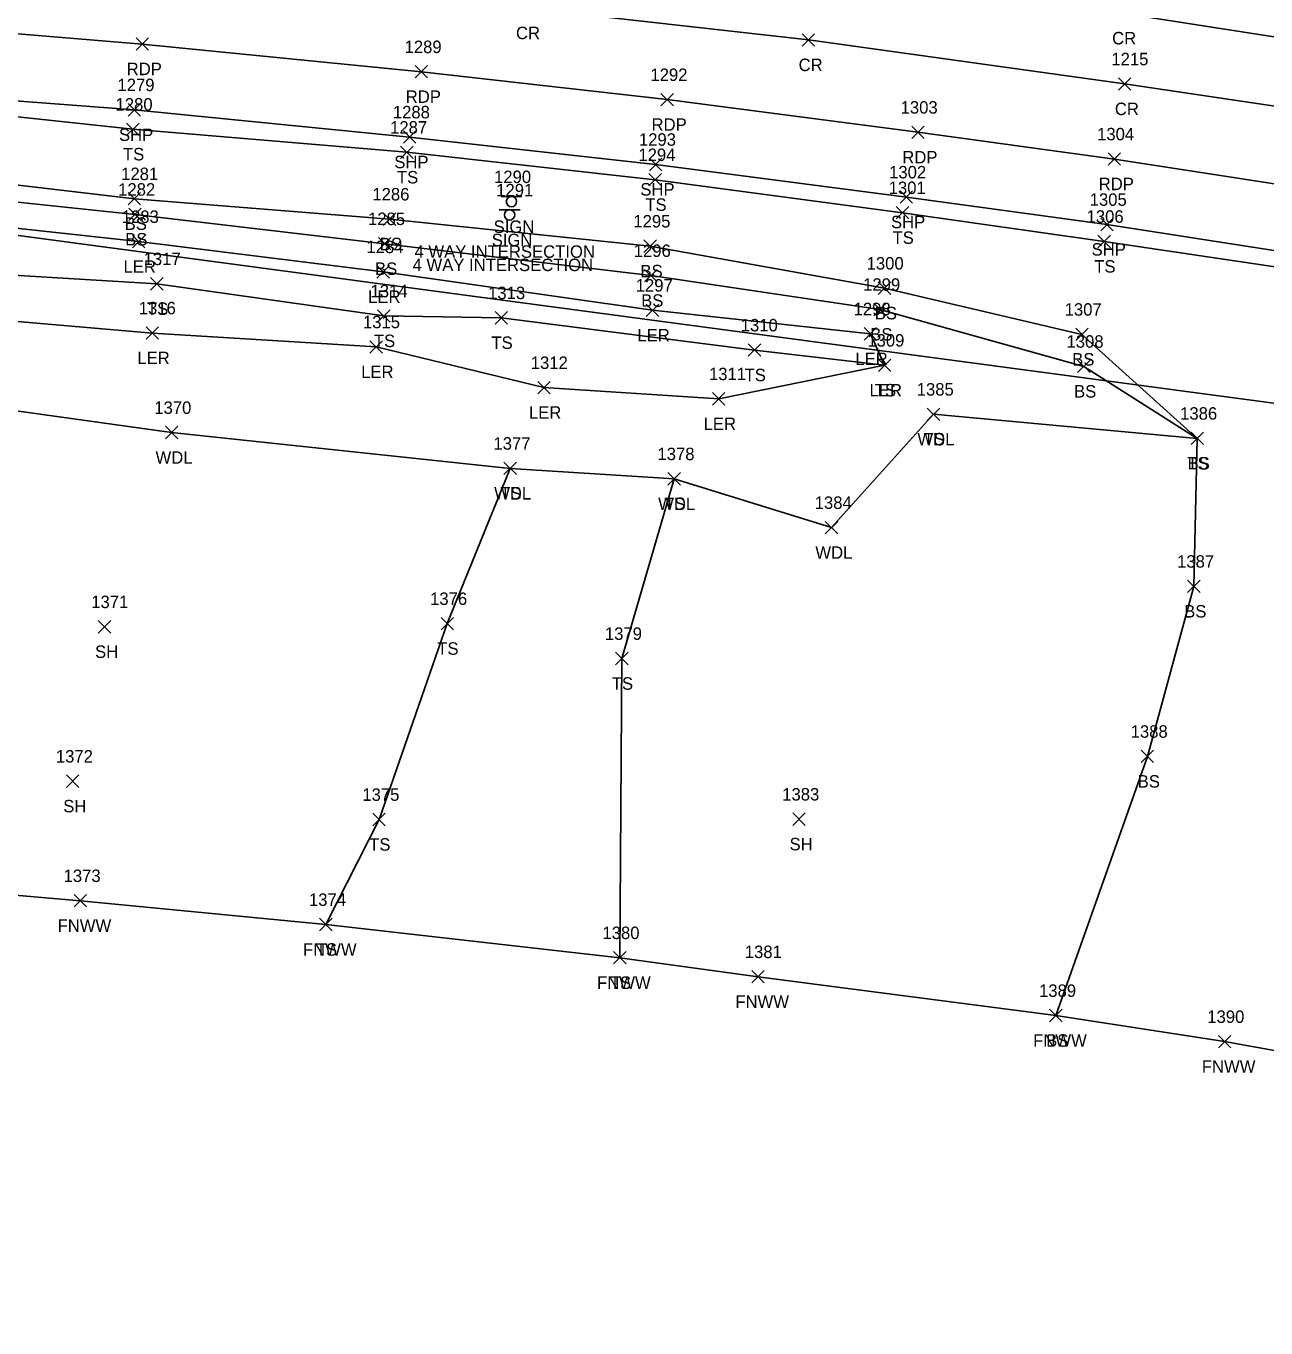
# Model space of a CAD drawing. Extents: x 1629176 to 1637209, y 606063 to 610167.
# Drawn here: x 1629364 to 1629563.1, y 606838.2 to 607047.2 of the extents above; entities that cross this region are included whole.
import ezdxf

# ---------------------------------------------------------------- set-up
doc = ezdxf.new("R2010")
doc.units = 0
for name, color, linetype in [('DCP', 7, 'Continuous'), ('L_A', 7, 'Continuous'), ('L_I', 7, 'Continuous'), ('L_TIC', 7, 'Continuous'), ('LARO', 7, 'Continuous'), ('LAWA', 7, 'Continuous'), ('LELB', 7, 'Continuous'), ('LFNC', 7, 'Continuous'), ('P_A', 7, 'Continuous'), ('P_I', 7, 'Continuous'), ('P_TIC', 7, 'Continuous'), ('PET', 7, 'Continuous'), ('PRC', 7, 'Continuous'), ('PSP', 7, 'Continuous'), ('S_A', 7, 'Continuous'), ('S_C', 7, 'Continuous'), ('S_I', 7, 'Continuous'), ('SSGN', 7, 'Continuous')]:
    doc.layers.add(name, color=color, linetype=linetype)

msp = doc.modelspace()

# ---------------------------------------------------------------- linework, layer by layer
at = {"layer": 'DCP'}
msp.add_lwpolyline([(1629240.18, 607029.98), (1629577.96, 606984.89)], dxfattribs=at)
at = {"layer": 'L_TIC'}
for points in [[(1629380.18, 607029.68), (1629382.18, 607031.68)], [(1629382.18, 607029.68), (1629380.18, 607031.68)], [(1629424.17, 607025.98), (1629426.17, 607027.98)], [(1629426.17, 607025.98), (1629424.17, 607027.98)], [(1629464.04, 607021.58), (1629466.04, 607023.58)], [(1629466.04, 607021.58), (1629464.04, 607023.58)], [(1629380.42, 607018.52), (1629382.42, 607020.52)], [(1629382.42, 607018.52), (1629380.42, 607020.52)], [(1629380.51, 607016.02), (1629382.51, 607018.02)], [(1629382.51, 607016.02), (1629380.51, 607018.02)], [(1629503.73, 607016.28), (1629505.73, 607018.28)], [(1629505.73, 607016.28), (1629503.73, 607018.28)], [(1629421.38, 607015.25), (1629423.38, 607017.25)], [(1629423.38, 607015.25), (1629421.38, 607017.25)], [(1629381.1, 607011.64), (1629383.1, 607013.64)], [(1629383.1, 607011.64), (1629381.1, 607013.64)], [(1629420.62, 607011.3), (1629422.62, 607013.3)], [(1629422.62, 607011.3), (1629420.62, 607013.3)], [(1629536.12, 607011.67), (1629538.12, 607013.67)], [(1629538.12, 607011.67), (1629536.12, 607013.67)], [(1629463.23, 607010.91), (1629465.23, 607012.91)], [(1629465.23, 607010.91), (1629463.23, 607012.91)], [(1629420.37, 607006.8), (1629422.37, 607008.8)], [(1629422.37, 607006.8), (1629420.37, 607008.8)], [(1629463.34, 607006.18), (1629465.34, 607008.18)], [(1629465.34, 607006.18), (1629463.34, 607008.18)], [(1629384.03, 607004.87), (1629386.03, 607006.87)], [(1629386.03, 607004.87), (1629384.03, 607006.87)], [(1629500.84, 607004.16), (1629502.84, 607006.16)], [(1629502.84, 607004.16), (1629500.84, 607006.16)], [(1629500.12, 607000.75), (1629502.12, 607002.75)], [(1629502.12, 607000.75), (1629500.12, 607002.75)], [(1629420.47, 606999.71), (1629422.47, 607001.71)], [(1629422.47, 606999.71), (1629420.47, 607001.71)], [(1629439.33, 606999.41), (1629441.33, 607001.41)], [(1629441.33, 606999.41), (1629439.33, 607001.41)], [(1629463.6, 607000.62), (1629465.6, 607002.62)], [(1629465.6, 607000.62), (1629463.6, 607002.62)], [(1629383.31, 606996.97), (1629385.31, 606998.97)], [(1629385.31, 606996.97), (1629383.31, 606998.97)], [(1629498.59, 606996.83), (1629500.59, 606998.83)], [(1629500.59, 606996.83), (1629498.59, 606998.83)], [(1629532.54, 606996.75), (1629534.54, 606998.75)], [(1629534.54, 606996.75), (1629532.54, 606998.75)], [(1629419.24, 606994.74), (1629421.24, 606996.74)], [(1629421.24, 606994.74), (1629419.24, 606996.74)], [(1629479.98, 606994.23), (1629481.98, 606996.23)], [(1629481.98, 606994.23), (1629479.98, 606996.23)], [(1629500.87, 606991.79), (1629502.87, 606993.79)], [(1629502.87, 606991.79), (1629500.87, 606993.79)], [(1629500.87, 606991.79), (1629502.87, 606993.79)], [(1629502.87, 606991.79), (1629500.87, 606993.79)], [(1629532.84, 606991.61), (1629534.84, 606993.61)], [(1629534.84, 606991.61), (1629532.84, 606993.61)], [(1629446.18, 606988.2), (1629448.18, 606990.2)], [(1629448.18, 606988.2), (1629446.18, 606990.2)], [(1629474.23, 606986.4), (1629476.23, 606988.4)], [(1629476.23, 606986.4), (1629474.23, 606988.4)], [(1629508.72, 606983.93), (1629510.72, 606985.93)], [(1629510.72, 606983.93), (1629508.72, 606985.93)], [(1629508.72, 606983.93), (1629510.72, 606985.93)], [(1629510.72, 606983.93), (1629508.72, 606985.93)], [(1629386.4, 606980.99), (1629388.4, 606982.99)], [(1629388.4, 606980.99), (1629386.4, 606982.99)], [(1629551.06, 606980.06), (1629553.06, 606982.06)], [(1629553.06, 606980.06), (1629551.06, 606982.06)], [(1629551.06, 606980.06), (1629553.06, 606982.06)], [(1629553.06, 606980.06), (1629551.06, 606982.06)], [(1629551.06, 606980.06), (1629553.06, 606982.06)], [(1629553.06, 606980.06), (1629551.06, 606982.06)], [(1629440.76, 606975.24), (1629442.76, 606977.24)], [(1629442.76, 606975.24), (1629440.76, 606977.24)], [(1629440.76, 606975.24), (1629442.76, 606977.24)], [(1629442.76, 606975.24), (1629440.76, 606977.24)], [(1629467.09, 606973.56), (1629469.09, 606975.56)], [(1629469.09, 606973.56), (1629467.09, 606975.56)], [(1629467.09, 606973.56), (1629469.09, 606975.56)], [(1629469.09, 606973.56), (1629467.09, 606975.56)], [(1629492.34, 606965.73), (1629494.34, 606967.73)], [(1629494.34, 606965.73), (1629492.34, 606967.73)], [(1629550.51, 606956.3), (1629552.51, 606958.3)], [(1629552.51, 606956.3), (1629550.51, 606958.3)], [(1629375.62, 606949.81), (1629377.62, 606951.81)], [(1629377.62, 606949.81), (1629375.62, 606951.81)], [(1629430.65, 606950.32), (1629432.65, 606952.32)], [(1629432.65, 606950.32), (1629430.65, 606952.32)], [(1629458.67, 606944.71), (1629460.67, 606946.71)], [(1629460.67, 606944.71), (1629458.67, 606946.71)], [(1629543.06, 606929), (1629545.06, 606931)], [(1629545.06, 606929), (1629543.06, 606931)], [(1629370.51, 606925.02), (1629372.51, 606927.02)], [(1629372.51, 606925.02), (1629370.51, 606927.02)], [(1629419.71, 606918.87), (1629421.71, 606920.87)], [(1629421.71, 606918.87), (1629419.71, 606920.87)], [(1629487.12, 606918.92), (1629489.12, 606920.92)], [(1629489.12, 606918.92), (1629487.12, 606920.92)], [(1629371.75, 606905.84), (1629373.75, 606907.84)], [(1629373.75, 606905.84), (1629371.75, 606907.84)], [(1629411.15, 606902.01), (1629413.15, 606904.01)], [(1629413.15, 606902.01), (1629411.15, 606904.01)], [(1629411.15, 606902.01), (1629413.15, 606904.01)], [(1629413.15, 606902.01), (1629411.15, 606904.01)], [(1629458.35, 606896.68), (1629460.35, 606898.68)], [(1629460.35, 606896.68), (1629458.35, 606898.68)], [(1629458.35, 606896.68), (1629460.35, 606898.68)], [(1629460.35, 606896.68), (1629458.35, 606898.68)], [(1629480.55, 606893.63), (1629482.55, 606895.63)], [(1629482.55, 606893.63), (1629480.55, 606895.63)], [(1629528.36, 606887.4), (1629530.36, 606889.4)], [(1629530.36, 606887.4), (1629528.36, 606889.4)], [(1629528.36, 606887.4), (1629530.36, 606889.4)], [(1629530.36, 606887.4), (1629528.36, 606889.4)], [(1629555.45, 606883.22), (1629557.45, 606885.22)], [(1629557.45, 606883.22), (1629555.45, 606885.22)]]:
    msp.add_lwpolyline(points, dxfattribs=at)
at = {"layer": 'LARO'}
msp.add_lwpolyline([(1629195.7, 607018.37), (1629216.28, 607024.93), (1629260.85, 607020.82), (1629301.15, 607020.1), (1629339.28, 607017.31), (1629382.1, 607012.64), (1629421.37, 607007.8), (1629464.6, 607001.62), (1629499.59, 606997.83), (1629501.87, 606992.79), (1629475.23, 606987.4), (1629447.18, 606989.2), (1629420.24, 606995.74), (1629384.31, 606997.97), (1629356.39, 607000.37), (1629322.81, 607000.42), (1629287.21, 607005.07), (1629251.47, 607005.2), (1629215.89, 607011.05), (1629196.49, 607014.19)], dxfattribs=at)
at = {"layer": 'LAWA'}
msp.add_lwpolyline([(1629337.05, 606990.15), (1629359.72, 606985.87), (1629387.4, 606981.99), (1629441.76, 606976.24), (1629468.09, 606974.56), (1629493.34, 606966.73), (1629509.72, 606984.93)], dxfattribs=at)
at = {"layer": 'LELB'}
for points in [[(1629181.05, 607042.55), (1629218.81, 607041.26), (1629263.39, 607039.5), (1629300.16, 607037.35), (1629342.16, 607034.85), (1629381.18, 607030.68), (1629425.17, 607026.98), (1629465.04, 607022.58), (1629504.73, 607017.28), (1629537.12, 607012.67), (1629575, 607007.04)], [(1629180.91, 607031.69), (1629217.04, 607032.99), (1629236.75, 607031.7), (1629261.62, 607030.75), (1629301.07, 607026.9), (1629340.53, 607024.3), (1629381.42, 607019.52), (1629422.38, 607016.25), (1629464.23, 607011.91), (1629501.84, 607005.16), (1629533.54, 606997.75), (1629552.06, 606981.06), (1629551.51, 606957.3), (1629544.06, 606930), (1629529.36, 606888.4)], [(1629180.79, 607027.59), (1629216.43, 607030.07), (1629237.58, 607029.18), (1629260.92, 607027.55), (1629301.36, 607024.43), (1629339.78, 607021.36), (1629381.51, 607017.02), (1629421.62, 607012.3), (1629464.34, 607007.18), (1629501.12, 607001.75), (1629533.84, 606992.61), (1629552.06, 606981.06)], [(1629501.87, 606992.79), (1629480.98, 606995.23), (1629440.33, 607000.41), (1629421.47, 607000.71), (1629385.03, 607005.87), (1629355.77, 607007.63), (1629321.41, 607007.24), (1629288.08, 607011.69), (1629252.51, 607015.34), (1629217.57, 607016.84), (1629196.49, 607014.19), (1629178.76, 606986.49), (1629181.84, 606967.24)], [(1629509.72, 606984.93), (1629552.06, 606981.06)], [(1629412.15, 606903.01), (1629420.71, 606919.87), (1629431.65, 606951.32), (1629441.76, 606976.24)], [(1629468.09, 606974.56), (1629459.67, 606945.71), (1629459.35, 606897.68)]]:
    msp.add_lwpolyline(points, dxfattribs=at)
at = {"layer": 'LFNC'}
msp.add_lwpolyline([(1629193.07, 606917.87), (1629225.59, 606916.68), (1629272.22, 606914.37), (1629291.9, 606913.28), (1629328.76, 606910.62), (1629372.75, 606906.84), (1629412.15, 606903.01), (1629459.35, 606897.68), (1629481.55, 606894.63), (1629529.36, 606888.4), (1629556.45, 606884.22), (1629596.1, 606877.05), (1629651.99, 606865.79), (1629687.21, 606857.94), (1629709.84, 606852.4), (1629726.11, 606849.55), (1629738.25, 606845.85), (1629771.23, 606838.25)], dxfattribs=at)
at = {"layer": 'P_TIC'}
for points in [[(1629381.7, 607043.36), (1629383.7, 607045.36)], [(1629383.7, 607043.36), (1629381.7, 607045.36)], [(1629488.63, 607044.02), (1629490.63, 607046.02)], [(1629490.63, 607044.02), (1629488.63, 607046.02)], [(1629426.5, 607038.91), (1629428.5, 607040.91)], [(1629428.5, 607038.91), (1629426.5, 607040.91)], [(1629539.4, 607036.95), (1629541.4, 607038.95)], [(1629541.4, 607036.95), (1629539.4, 607038.95)], [(1629465.96, 607034.43), (1629467.96, 607036.43)], [(1629467.96, 607034.43), (1629465.96, 607036.43)], [(1629380.41, 607032.8), (1629382.41, 607034.8)], [(1629382.41, 607032.8), (1629380.41, 607034.8)], [(1629424.61, 607028.43), (1629426.61, 607030.43)], [(1629426.61, 607028.43), (1629424.61, 607030.43)], [(1629506.21, 607029.19), (1629508.21, 607031.19)], [(1629508.21, 607029.19), (1629506.21, 607031.19)], [(1629464.11, 607024.03), (1629466.11, 607026.03)], [(1629466.11, 607024.03), (1629464.11, 607026.03)], [(1629537.75, 607024.9), (1629539.75, 607026.9)], [(1629539.75, 607024.9), (1629537.75, 607026.9)], [(1629504.36, 607018.79), (1629506.36, 607020.79)], [(1629506.36, 607018.79), (1629504.36, 607020.79)], [(1629536.56, 607014.39), (1629538.56, 607016.39)], [(1629538.56, 607014.39), (1629536.56, 607016.39)]]:
    msp.add_lwpolyline(points, dxfattribs=at)
at = {"layer": 'PET'}
msp.add_lwpolyline([(1629181.97, 607055.08), (1629220.58, 607054.17), (1629264.89, 607052.3), (1629300.55, 607050.62), (1629344.63, 607047.49), (1629382.7, 607044.36), (1629427.5, 607039.91), (1629466.96, 607035.43), (1629507.21, 607030.19), (1629538.75, 607025.9), (1629578.99, 607019.69), (1629624.23, 607012.05), (1629673.21, 607003.11), (1629718.04, 606993.87), (1629764.48, 606983.46), (1629805.04, 606973.93), (1629842.82, 606964.4), (1629884.8, 606953.15), (1629930.25, 606940.34), (1629964.97, 606930.13), (1630005.89, 606916.45), (1630050.76, 606901.68), (1630096.23, 606885.67)], dxfattribs=at)
at = {"layer": 'PRC'}
for points in [[(1630110.18, 606905.77), (1630065.36, 606921.68), (1630022.36, 606935.68), (1629994.71, 606945.36), (1629959.54, 606955.86), (1629913.54, 606969.37), (1629877.41, 606979.26), (1629837.69, 606989.99), (1629791.63, 607000.82), (1629746.42, 607011.44), (1629699.59, 607021.37), (1629664.04, 607028.34), (1629619.43, 607036.79), (1629585.72, 607042.18), (1629539.96, 607049.3), (1629491.45, 607056.02), (1629445.88, 607061.28), (1629404.36, 607066.23), (1629358.89, 607069.49), (1629314.63, 607073.29), (1629269.37, 607075.36), (1629226.58, 607077.32), (1629182.35, 607078.58)], [(1630105.99, 606894.95), (1630061.18, 606910.94), (1630017.61, 606925.74), (1629991.01, 606934.32), (1629955.3, 606944.84), (1629910.77, 606959.12), (1629874.52, 606969.06), (1629834.93, 606979.4), (1629788.74, 606990.13), (1629743.3, 607000.68), (1629697.98, 607010.33), (1629662.17, 607017.56), (1629618.2, 607025.81), (1629583.59, 607031.56), (1629540.4, 607037.95), (1629489.63, 607045.02), (1629444.26, 607050.14), (1629402.79, 607054.66), (1629359.1, 607058.26), (1629313.06, 607061.88), (1629268.47, 607063.97), (1629226.23, 607065.89), (1629182.22, 607066.96)]]:
    msp.add_lwpolyline(points, dxfattribs=at)
at = {"layer": 'PSP'}
msp.add_lwpolyline([(1629181.26, 607044.82), (1629219.33, 607043.61), (1629263.7, 607041.6), (1629300.14, 607039.68), (1629342.49, 607036.76), (1629381.41, 607033.8), (1629425.61, 607029.43), (1629465.11, 607025.03), (1629505.36, 607019.79), (1629537.56, 607015.39), (1629576.08, 607009.38), (1629623.28, 607001.72), (1629671.03, 606992.73), (1629715.19, 606983.38), (1629761.23, 606973.52), (1629802.25, 606963.72), (1629839.3, 606954.1), (1629871.33, 606945.94), (1629930.37, 606928.51), (1629965.2, 606918.43), (1630003.07, 606906.25), (1630045.28, 606892.75), (1630092.08, 606875.64)], dxfattribs=at)
at = {"layer": 'SSGN'}
for p, q in [((1629440.31, 607019.89), (1629443.65, 607019.89)), ((1629440.01, 607017.76), (1629443.34, 607017.76)), ((1629441.96, 607019.06), (1629441.96, 607019.06)), ((1629441.66, 607016.93), (1629441.66, 607016.93))]:
    msp.add_line(p, q, dxfattribs=at)
for centre in [(1629441.96, 607019.06), (1629441.66, 607016.93)]:
    msp.add_circle(centre, 0.833, dxfattribs=at)

# ---------------------------------------------------------------- texts
at = {"layer": 'L_A'}
for s, p in [('TS', (1629379.59, 607025.68)), ('TS', (1629423.58, 607021.98)), ('TS', (1629463.45, 607017.58)), ('BS', (1629379.87, 607014.52)), ('BS', (1629379.95, 607012.02)), ('BS', (1629420.82, 607011.25)), ('TS', (1629503.14, 607012.28)), ('LER', (1629379.68, 607007.64)), ('BS', (1629420.06, 607007.3)), ('TS', (1629535.53, 607007.67)), ('BS', (1629462.67, 607006.91)), ('TS', (1629383.44, 607000.87)), ('LER', (1629418.95, 607002.8)), ('BS', (1629462.78, 607002.18)), ('BS', (1629500.28, 607000.16)), ('LER', (1629462.18, 606996.62)), ('BS', (1629499.56, 606996.75)), ('TS', (1629419.88, 606995.71)), ('TS', (1629438.74, 606995.41)), ('LER', (1629381.9, 606992.97)), ('LER', (1629497.17, 606992.83)), ('BS', (1629531.98, 606992.75)), ('LER', (1629417.83, 606990.74)), ('TS', (1629479.39, 606990.23)), ('LER', (1629499.45, 606987.79)), ('TS', (1629500.28, 606987.79)), ('BS', (1629532.28, 606987.61)), ('LER', (1629444.77, 606984.2)), ('LER', (1629472.81, 606982.4)), ('WDL', (1629507.13, 606979.93)), ('TS', (1629508.13, 606979.93)), ('WDL', (1629384.82, 606976.99)), ('TS', (1629550.47, 606976.06)), ('BS', (1629550.5, 606976.06)), ('BS', (1629550.5, 606976.06)), ('WDL', (1629439.18, 606971.24)), ('TS', (1629440.17, 606971.24)), ('WDL', (1629465.51, 606969.56)), ('TS', (1629466.5, 606969.56)), ('WDL', (1629490.75, 606961.73)), ('BS', (1629549.96, 606952.3)), ('SH', (1629375.11, 606945.81)), ('TS', (1629430.05, 606946.32)), ('TS', (1629458.07, 606940.71)), ('BS', (1629542.5, 606925)), ('SH', (1629370, 606921.02)), ('TS', (1629419.12, 606914.87)), ('SH', (1629486.61, 606914.92)), ('FNWW', (1629369.1, 606901.84)), ('FNWW', (1629408.49, 606898.01)), ('TS', (1629410.56, 606898.01)), ('FNWW', (1629455.7, 606892.68)), ('TS', (1629457.76, 606892.68)), ('FNWW', (1629477.9, 606889.63)), ('FNWW', (1629525.71, 606883.4)), ('BS', (1629527.8, 606883.4)), ('FNWW', (1629552.79, 606879.22))]:
    msp.add_text(s, height=2, dxfattribs=at).set_placement(p)
at = {"layer": 'L_I'}
for s, p in [('1280', (1629378.4, 607033.68)), ('1287', (1629422.48, 607029.98)), ('1294', (1629462.34, 607025.58)), ('1281', (1629379.3, 607022.52)), ('1282', (1629378.82, 607020.02)), ('1301', (1629502.52, 607020.28)), ('1286', (1629419.63, 607019.25)), ('1283', (1629379.4, 607015.64)), ('1306', (1629534.29, 607015.67)), ('1285', (1629418.93, 607015.3)), ('1295', (1629461.53, 607014.91)), ('1284', (1629418.67, 607010.8)), ('1296', (1629461.59, 607010.18)), ('1317', (1629382.91, 607008.87)), ('1300', (1629498.98, 607008.16)), ('1314', (1629419.34, 607003.71)), ('1313', (1629438.21, 607003.41)), ('1297', (1629461.91, 607004.62)), ('1299', (1629498.42, 607004.75)), ('1316', (1629382.13, 607000.97)), ('1298', (1629496.89, 607000.83)), ('1307', (1629530.77, 607000.75)), ('1315', (1629418.12, 606998.74)), ('1310', (1629478.77, 606998.23)), ('1309', (1629499.09, 606995.79)), ('1309', (1629499.09, 606995.79)), ('1308', (1629531.07, 606995.61)), ('1312', (1629445.06, 606992.2)), ('1311', (1629473.67, 606990.4)), ('1385', (1629507.02, 606987.93)), ('1385', (1629507.02, 606987.93)), ('1370', (1629384.62, 606984.99)), ('1386', (1629549.31, 606984.06)), ('1386', (1629549.31, 606984.06)), ('1386', (1629549.31, 606984.06)), ('1377', (1629439.07, 606979.24)), ('1377', (1629439.07, 606979.24)), ('1378', (1629465.4, 606977.56)), ('1378', (1629465.4, 606977.56)), ('1384', (1629490.64, 606969.73)), ('1387', (1629548.82, 606960.3)), ('1371', (1629374.5, 606953.81)), ('1376', (1629428.9, 606954.32)), ('1379', (1629456.96, 606948.71)), ('1388', (1629541.37, 606933)), ('1372', (1629368.82, 606929.02)), ('1375', (1629418.02, 606922.87)), ('1383', (1629485.43, 606922.92)), ('1373', (1629370.06, 606909.84)), ('1374', (1629409.45, 606906.01)), ('1374', (1629409.45, 606906.01)), ('1380', (1629456.57, 606900.68)), ('1380', (1629456.57, 606900.68)), ('1381', (1629479.42, 606897.63)), ('1389', (1629526.66, 606891.4)), ('1389', (1629526.66, 606891.4)), ('1390', (1629553.67, 606887.22))]:
    msp.add_text(s, height=2, dxfattribs=at).set_placement(p)
at = {"layer": 'P_A'}
for s, p in [('CR', (1629442.69, 607045.14)), ('CR', (1629538.39, 607044.3)), ('RDP', (1629380.19, 607039.36)), ('CR', (1629488.06, 607040.02)), ('RDP', (1629424.99, 607034.91)), ('CR', (1629538.83, 607032.95)), ('RDP', (1629464.45, 607030.43)), ('SHP', (1629378.95, 607028.8)), ('SHP', (1629423.15, 607024.43)), ('RDP', (1629504.7, 607025.19)), ('SHP', (1629462.65, 607020.03)), ('RDP', (1629536.24, 607020.9)), ('SHP', (1629502.89, 607014.79)), ('SHP', (1629535.1, 607010.39))]:
    msp.add_text(s, height=2, dxfattribs=at).set_placement(p)
at = {"layer": 'P_I'}
for s, p in [('1289', (1629424.8, 607042.91)), ('1215', (1629538.27, 607040.95)), ('1292', (1629464.27, 607038.43)), ('1279', (1629378.71, 607036.8)), ('1288', (1629422.92, 607032.43)), ('1303', (1629504.44, 607033.19)), ('1293', (1629462.42, 607028.03)), ('1304', (1629535.98, 607028.9)), ('1302', (1629502.59, 607022.79)), ('1305', (1629534.79, 607018.39))]:
    msp.add_text(s, height=2, dxfattribs=at).set_placement(p)
at = {"layer": 'S_A'}
for p in [(1629439.1, 607014.04), (1629438.79, 607011.91)]:
    msp.add_text('SIGN', height=2, dxfattribs=at).set_placement(p)
at = {"layer": 'S_C'}
for p in [(1629426.39, 607010.04), (1629426.09, 607007.91)]:
    msp.add_text('4 WAY INTERSECTION', height=2, dxfattribs=at).set_placement(p)
at = {"layer": 'S_I'}
for s, p in [('1290', (1629439.16, 607022.04)), ('1291', (1629439.51, 607019.91))]:
    msp.add_text(s, height=2, dxfattribs=at).set_placement(p)

doc.saveas('drawing.dxf')
